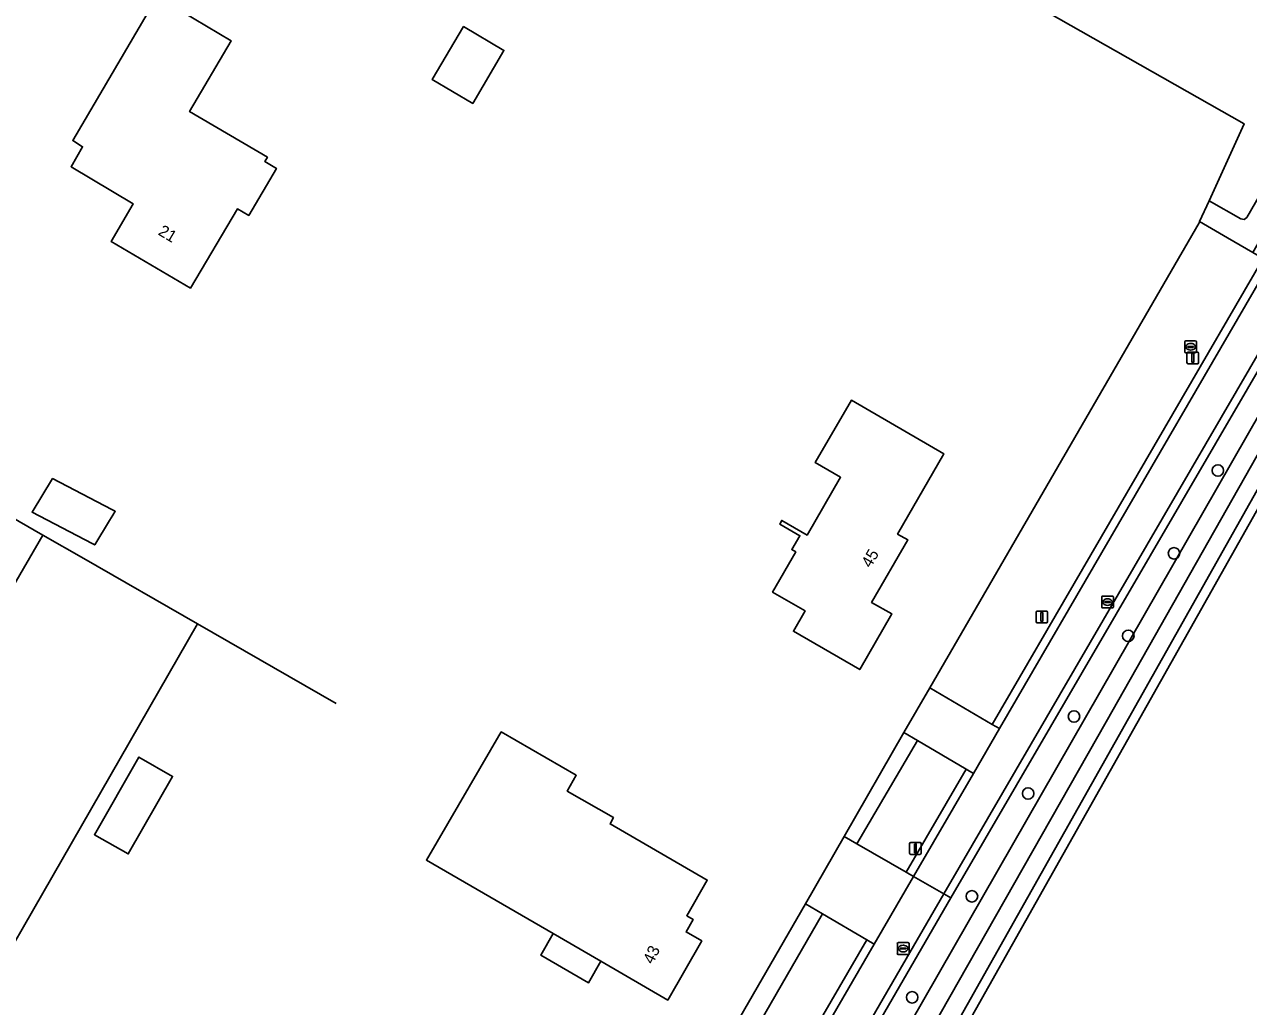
# Model space of a CAD drawing. Extents: x 156502 to 159075, y 384229 to 386100.
# Drawn here: x 157270.5 to 157374.9, y 385779.8 to 385863.6 of the extents above; entities that cross this region are included whole.
import ezdxf

# ---------------------------------------------------------------- set-up
doc = ezdxf.new("R2010")
doc.units = 0
for name, color, linetype in [('IMGEO_Boom', 7, 'Continuous'), ('IMGEO_Erf', 7, 'Continuous'), ('IMGEO_Gemengd_bos', 7, 'Continuous'), ('IMGEO_Grasland_overig', 7, 'Continuous'), ('IMGEO_Greppel_droge_sloot', 7, 'Continuous'), ('IMGEO_Groenvoorziening', 7, 'Continuous'), ('IMGEO_Hek', 7, 'Continuous'), ('IMGEO_Lichtmast', 7, 'Continuous'), ('IMGEO_Oever', 7, 'Continuous'), ('IMGEO_Pand', 7, 'Continuous'), ('IMGEO_Pand_nummerreeks', 7, 'Continuous'), ('IMGEO_Pand_overbouw', 7, 'Continuous'), ('IMGEO_Rijbaan_lokaal_gesloten', 7, 'Continuous'), ('IMGEO_Rijbaan_lokaal_halfverhard', 7, 'Continuous'), ('IMGEO_Rijbaan_lokaal_open', 7, 'Continuous'), ('IMGEO_Rioolput', 7, 'Continuous')]:
    doc.layers.add(name, color=color, linetype=linetype)

msp = doc.modelspace()

# ---------------------------------------------------------------- linework, layer by layer
at = {"layer": 'IMGEO_Boom'}
for centre in [(157372.3, 385825.54), (157368.55, 385818.48), (157364.65, 385811.44), (157360.02, 385804.56), (157356.1, 385798), (157351.31, 385789.23), (157346.21, 385780.62)]:
    msp.add_circle(centre, 0.489, dxfattribs=at)
at = {"layer": 'IMGEO_Erf'}
msp.add_lwpolyline([(157260.44, 385826.72), (157272.04, 385820.04), (157275.52, 385818.05), (157285.22, 385812.46), (157254.63, 385759.26), (157295.91, 385735.36), (157303.57, 385730.97), (157303.66, 385730.92), (157313.86, 385748.5), (157317.18, 385754.23), (157317.26, 385754.36), (157320.72, 385760.25), (157337.11, 385788.6), (157340.4, 385794.34), (157345.49, 385803.19), (157347.71, 385807.02), (157370.69, 385846.65), (157370.74, 385846.77), (157371.55, 385848.55), (157374.53, 385855.11), (157336.95, 385876.45)], dxfattribs=at)
for points in [[(157281.78, 385865.95), (157288.1, 385862.19), (157284.56, 385856.15), (157291.2, 385852.25), (157290.98, 385851.88), (157291.96, 385851.3), (157289.6, 385847.29), (157288.63, 385847.85), (157284.62, 385841.1), (157277.86, 385845.08), (157279.74, 385848.29), (157274.44, 385851.45), (157275.43, 385853.15), (157274.59, 385853.67)], [(157307.93, 385863.4), (157311.38, 385861.36), (157308.71, 385856.84), (157305.26, 385858.88)], [(157341.02, 385831.54), (157348.92, 385826.96), (157344.96, 385820.12), (157345.83, 385819.63), (157342.75, 385814.3), (157344.48, 385813.31), (157341.74, 385808.56), (157336.08, 385811.83), (157337.08, 385813.57), (157334.3, 385815.17), (157336.28, 385818.6), (157335.94, 385818.8), (157336.63, 385819.98), (157334.91, 385820.98), (157335.08, 385821.29), (157337.24, 385820.04), (157340.1, 385824.97), (157337.94, 385826.22)], [(157277.91, 385822.23), (157278.21, 385822.07), (157278, 385821.73), (157277.73, 385821.28), (157276.46, 385819.2), (157276.24, 385819.31), (157271.12, 385821.98), (157272.87, 385824.85)], [(157317.55, 385799.56), (157316.78, 385798.21), (157320.72, 385795.94), (157320.43, 385795.41), (157328.72, 385790.61), (157326.97, 385787.58), (157327.53, 385787.24), (157326.92, 385786.2), (157328.26, 385785.43), (157325.36, 385780.38), (157319.65, 385783.69), (157315.58, 385786.05), (157304.76, 385792.32), (157311.15, 385803.25)], [(157280.23, 385801.1), (157283.1, 385799.46), (157279.32, 385792.84), (157276.44, 385794.48)]]:
    msp.add_lwpolyline(points, close=True, dxfattribs=at)
at = {"layer": 'IMGEO_Gemengd_bos'}
for points in [[(157202.77, 386052.01), (157197.24, 386050.03), (157178.39, 386025.76), (157218.89, 386000), (157265.45, 385970.38), (157240.01, 385933.44), (157257.61, 385922.62), (157291.8, 385905.79), (157297.29, 385911.48), (157341.88, 385885.73), (157336.95, 385876.45), (157374.53, 385855.11), (157371.55, 385848.55), (157374.24, 385846.99), (157374.53, 385846.95), (157374.77, 385847.13), (157419.09, 385923.89)], [(157458.7, 385822.57), (157423.67, 385843.01), (157401.01, 385856.04), (157400.45, 385856.36), (157400.33, 385856.13), (157400.02, 385856.3), (157396.13, 385858.5), (157395.47, 385857.33), (157372.59, 385816.74), (157334.96, 385750), (157287.88, 385668.68), (157271.39, 385640.19), (157191.03, 385500)]]:
    msp.add_lwpolyline(points, dxfattribs=at)
msp.add_lwpolyline([(157285.22, 385812.46), (157275.52, 385818.05), (157272.04, 385820.04), (157246.93, 385776.79), (157242.96, 385769.96), (157222.97, 385734.27), (157232.44, 385728.12), (157250.89, 385753.43), (157300.61, 385725.63), (157300.68, 385725.75), (157301.99, 385728.11), (157303.57, 385730.97), (157295.91, 385735.36), (157254.63, 385759.26)], close=True, dxfattribs=at)
at = {"layer": 'IMGEO_Grasland_overig'}
for points in [[(157272.04, 385820.04), (157260.44, 385826.72), (157250.7, 385832.31), (157250.46, 385831.88), (157205.7, 385857.93)], [(157186.51, 385823.49), (157214.2, 385807.37), (157215.15, 385806.82), (157210.12, 385798.13), (157215.69, 385794.81), (157216.71, 385794.2), (157246.93, 385776.79), (157272.04, 385820.04)]]:
    msp.add_lwpolyline(points, dxfattribs=at)
at = {"layer": 'IMGEO_Greppel_droge_sloot'}
for points in [[(157419.09, 385923.89), (157374.77, 385847.13), (157374.53, 385846.95), (157374.24, 385846.99), (157371.55, 385848.55), (157370.74, 385846.77), (157373.11, 385845.39), (157375.29, 385844.13), (157410.37, 385905.3), (157420.59, 385922.78), (157421.74, 385925.12)], [(157393.36, 385858.05), (157393.11, 385857.61), (157362.75, 385804.11), (157325.82, 385739.17), (157293.92, 385684.22), (157277.51, 385655.56), (157259.26, 385623.71), (157238.62, 385587.75), (157224.85, 385563.79), (157203.07, 385525.9), (157174.27, 385475.36), (157161.25, 385452.05), (157151.08, 385433.93), (157146.7, 385427.27), (157144.86, 385424.97)], [(157146.46, 385424.36), (157148.98, 385428.05), (157150.58, 385430.99), (157151.89, 385433.4), (157190.31, 385500.41), (157270.67, 385640.6), (157287.16, 385669.09), (157334.24, 385750.41), (157371.86, 385817.15), (157394.6, 385857.47)]]:
    msp.add_lwpolyline(points, dxfattribs=at)
at = {"layer": 'IMGEO_Groenvoorziening'}
for points in [[(157395.47, 385857.33), (157396.13, 385858.5), (157400.02, 385856.3), (157400.33, 385856.13), (157400.45, 385856.36), (157394.87, 385860.03), (157394.47, 385860.19), (157394.07, 385860.35), (157391.83, 385861.67), (157349.52, 385789.09), (157310.6, 385721.93), (157305.61, 385713.27), (157297.81, 385699.74), (157287.9, 385682.57), (157281.97, 385672.23), (157284.2, 385670.89), (157329.73, 385750)], [(157329.73, 385750), (157392.25, 385858.97)]]:
    msp.add_lwpolyline(points, dxfattribs=at)
for points in [[(157347.71, 385807.02), (157353.05, 385803.89), (157376.15, 385843.62), (157375.29, 385844.13), (157373.11, 385845.39), (157370.74, 385846.77), (157370.69, 385846.65)], [(157346.66, 385802.51), (157345.49, 385803.19), (157340.4, 385794.34), (157341.5, 385793.71)], [(157350.82, 385800.07), (157346.66, 385802.51), (157341.5, 385793.71), (157345.7, 385791.29)], [(157338.56, 385787.75), (157337.11, 385788.6), (157320.72, 385760.25), (157317.26, 385754.36), (157318.78, 385753.48)], [(157342.35, 385785.53), (157338.56, 385787.75), (157318.78, 385753.48), (157322.45, 385751.34)]]:
    msp.add_lwpolyline(points, close=True, dxfattribs=at)
at = {"layer": 'IMGEO_Hek'}
for points in [[(157240.01, 385933.44), (157257.61, 385922.62), (157291.8, 385905.79), (157297.29, 385911.48), (157341.88, 385885.73), (157336.95, 385876.45), (157374.53, 385855.11), (157371.55, 385848.55)], [(157372.59, 385816.74), (157395.47, 385857.33)], [(157371.55, 385848.55), (157370.74, 385846.77)], [(157370.74, 385846.77), (157370.69, 385846.65), (157347.71, 385807.02)], [(157260.44, 385826.72), (157272.04, 385820.04)], [(157272.04, 385820.04), (157275.52, 385818.05)], [(157275.52, 385818.05), (157285.22, 385812.46)], [(157334.96, 385750), (157372.59, 385816.74)], [(157295.91, 385735.36), (157254.63, 385759.26), (157285.22, 385812.46)], [(157285.22, 385812.46), (157297.05, 385805.66)], [(157347.71, 385807.02), (157345.49, 385803.19)], [(157345.49, 385803.19), (157340.4, 385794.34)], [(157320.72, 385760.25), (157337.11, 385788.6)]]:
    msp.add_lwpolyline(points, dxfattribs=at)
at = {"layer": 'IMGEO_Lichtmast'}
for p, q in [((157369.76, 385835.64), (157370.55, 385835.64)), ((157370.55, 385835.64), (157369.76, 385835.64)), ((157369.66, 385834.74), (157369.66, 385835.54)), ((157369.66, 385835.54), (157369.66, 385834.74)), ((157370.55, 385834.64), (157369.76, 385834.64)), ((157369.76, 385834.64), (157370.55, 385834.64)), ((157370.65, 385835.54), (157370.65, 385834.74)), ((157370.65, 385834.74), (157370.65, 385835.54)), ((157356.78, 385812.66), (157356.78, 385813.46)), ((157356.78, 385813.46), (157356.78, 385812.66)), ((157356.88, 385813.56), (157357.67, 385813.56)), ((157357.67, 385813.56), (157356.88, 385813.56)), ((157357.77, 385813.46), (157357.77, 385812.66)), ((157357.77, 385812.66), (157357.77, 385813.46)), ((157357.67, 385812.56), (157356.88, 385812.56)), ((157356.88, 385812.56), (157357.67, 385812.56)), ((157345.99, 385792.91), (157345.99, 385793.71)), ((157345.99, 385793.71), (157345.99, 385792.91)), ((157346.09, 385793.81), (157346.88, 385793.81)), ((157346.88, 385793.81), (157346.09, 385793.81)), ((157346.88, 385792.81), (157346.09, 385792.81)), ((157346.09, 385792.81), (157346.88, 385792.81)), ((157346.98, 385793.71), (157346.98, 385792.91)), ((157346.98, 385792.91), (157346.98, 385793.71))]:
    msp.add_line(p, q, dxfattribs=at)
for points in [[(157370.08, 385835.52), (157370.23, 385835.52), (157370.23, 385834.77), (157370.08, 385834.77), (157370.08, 385835.52)], [(157357.2, 385813.43), (157357.35, 385813.43), (157357.35, 385812.68), (157357.2, 385812.68), (157357.2, 385813.43)], [(157346.41, 385793.69), (157346.56, 385793.69), (157346.56, 385792.94), (157346.41, 385792.94), (157346.41, 385793.69)]]:
    msp.add_lwpolyline(points, dxfattribs=at)
for centre, start, end in [((157369.76, 385835.54), 90, 180), ((157369.76, 385835.54), 90, 180), ((157370.55, 385835.54), 0, 90), ((157370.55, 385835.54), 360, 90), ((157369.76, 385834.74), 180, 270), ((157369.76, 385834.74), 180, 270), ((157370.55, 385834.74), 270, 0), ((157370.55, 385834.74), 270, 0), ((157356.88, 385813.46), 90, 180), ((157356.88, 385813.46), 90, 180), ((157356.88, 385812.66), 180, 270), ((157356.88, 385812.66), 180, 270), ((157357.67, 385813.46), 0, 90), ((157357.67, 385813.46), 360, 90), ((157357.67, 385812.66), 270, 0), ((157357.67, 385812.66), 270, 0), ((157346.09, 385793.71), 90, 180), ((157346.09, 385793.71), 90, 180), ((157346.09, 385792.91), 180, 270), ((157346.09, 385792.91), 180, 270), ((157346.88, 385793.71), 0, 90), ((157346.88, 385793.71), 360, 90), ((157346.88, 385792.91), 270, 0), ((157346.88, 385792.91), 270, 0)]:
    msp.add_arc(centre, 0.1, start, end, dxfattribs=at)
at = {"layer": 'IMGEO_Oever'}
for points in [[(157392.25, 385858.97), (157329.73, 385750), (157284.2, 385670.89), (157172.1, 385476.13), (157169.19, 385471.06), (157144.41, 385428.01), (157142.39, 385426.07), (157140.63, 385424.94), (157139.2, 385424.57), (157138.03, 385424.77), (157136.95, 385425.17), (157066.81, 385467.26), (157031.92, 385488.2), (156971.45, 385524.49), (156960.96, 385531.06), (156958.28, 385532.65)], [(157144.86, 385424.97), (157146.7, 385427.27), (157151.08, 385433.93), (157161.25, 385452.05), (157174.27, 385475.36), (157203.07, 385525.9), (157224.85, 385563.79), (157238.62, 385587.75), (157259.26, 385623.71), (157277.51, 385655.56), (157293.92, 385684.22), (157325.82, 385739.17), (157362.75, 385804.11), (157393.11, 385857.61), (157393.36, 385858.05)], [(157146.17, 385421.74), (157150.67, 385429.59), (157152.55, 385432.88), (157191.03, 385500), (157271.39, 385640.19), (157287.88, 385668.68), (157334.96, 385750), (157372.59, 385816.74), (157395.47, 385857.33)], [(157394.6, 385857.47), (157371.86, 385817.15), (157334.24, 385750.41), (157287.16, 385669.09), (157270.67, 385640.6), (157190.31, 385500.41), (157151.89, 385433.4), (157150.58, 385430.99), (157148.98, 385428.05), (157146.46, 385424.36)]]:
    msp.add_lwpolyline(points, dxfattribs=at)
at = {"layer": 'IMGEO_Pand'}
for points in [[(157281.78, 385865.95), (157274.59, 385853.67), (157275.43, 385853.15), (157274.44, 385851.45), (157279.74, 385848.29), (157277.86, 385845.08), (157284.62, 385841.1), (157288.63, 385847.85), (157289.6, 385847.29), (157291.96, 385851.3), (157290.98, 385851.88), (157291.2, 385852.25), (157284.56, 385856.15), (157288.1, 385862.19)], [(157305.26, 385858.88), (157308.71, 385856.84), (157311.38, 385861.36), (157307.93, 385863.4)], [(157348.92, 385826.96), (157341.02, 385831.54), (157337.94, 385826.22), (157340.1, 385824.97), (157337.24, 385820.04), (157335.08, 385821.29), (157334.91, 385820.98), (157336.63, 385819.98), (157335.94, 385818.8), (157336.28, 385818.6), (157334.3, 385815.17), (157337.08, 385813.57), (157336.08, 385811.83), (157341.74, 385808.56), (157344.48, 385813.31), (157342.75, 385814.3), (157345.83, 385819.63), (157344.96, 385820.12)], [(157272.87, 385824.85), (157271.12, 385821.98), (157276.24, 385819.31), (157276.46, 385819.2), (157277.73, 385821.28), (157278, 385821.73), (157278.21, 385822.07), (157277.91, 385822.23)], [(157320.43, 385795.41), (157320.72, 385795.94), (157316.78, 385798.21), (157317.55, 385799.56), (157311.15, 385803.25), (157304.76, 385792.32), (157315.58, 385786.05), (157319.65, 385783.69), (157325.36, 385780.38), (157328.26, 385785.43), (157326.92, 385786.2), (157327.53, 385787.24), (157326.97, 385787.58), (157328.72, 385790.61)], [(157283.1, 385799.46), (157280.23, 385801.1), (157276.44, 385794.48), (157279.32, 385792.84)]]:
    msp.add_lwpolyline(points, close=True, dxfattribs=at)
at = {"layer": 'IMGEO_Pand_overbouw'}
msp.add_lwpolyline([(157315.58, 385786.05), (157314.52, 385784.22), (157318.6, 385781.86), (157319.65, 385783.69)], close=True, dxfattribs=at)
at = {"layer": 'IMGEO_Rijbaan_lokaal_gesloten'}
msp.add_lwpolyline([(157348.91, 385789.44), (157391.21, 385862.03), (157396.12, 385870.48), (157427.36, 385924.19), (157427.79, 385923.96), (157432.64, 385928.52), (157423.54, 385933.72), (157425.1, 385927.64), (157424.2, 385926.06), (157424.73, 385925.73), (157353.67, 385803.53), (157351.44, 385799.71), (157346.33, 385790.92)], close=True, dxfattribs=at)
at = {"layer": 'IMGEO_Rijbaan_lokaal_halfverhard'}
for points in [[(157424.73, 385925.73), (157424.2, 385926.06), (157424.08, 385926.09), (157423.29, 385924.72), (157376.15, 385843.62), (157353.05, 385803.89), (157353.67, 385803.53)], [(157391.83, 385861.67), (157391.21, 385862.03), (157348.91, 385789.44), (157349.52, 385789.09)], [(157353.67, 385803.53), (157353.05, 385803.89), (157347.71, 385807.02), (157345.49, 385803.19), (157346.66, 385802.51), (157350.82, 385800.07), (157351.44, 385799.71)], [(157351.44, 385799.71), (157350.82, 385800.07), (157345.7, 385791.29), (157346.33, 385790.92)], [(157349.52, 385789.09), (157348.91, 385789.44), (157309.98, 385722.29), (157304.98, 385713.63), (157297.19, 385700.1), (157287.28, 385682.93), (157276.98, 385664.99), (157272.99, 385658.15), (157259.7, 385634.92), (157260.02, 385634.73), (157260.32, 385634.56), (157273.62, 385657.79), (157277.6, 385664.64), (157281.97, 385672.23), (157287.9, 385682.57), (157297.81, 385699.74), (157305.61, 385713.27), (157310.6, 385721.93)], [(157342.98, 385785.16), (157342.35, 385785.53), (157322.45, 385751.34), (157323.12, 385750.95)]]:
    msp.add_lwpolyline(points, close=True, dxfattribs=at)
at = {"layer": 'IMGEO_Rijbaan_lokaal_open'}
msp.add_lwpolyline([(157346.33, 385790.92), (157345.7, 385791.29), (157341.5, 385793.71), (157340.4, 385794.34), (157337.11, 385788.6), (157338.56, 385787.75), (157342.35, 385785.53), (157342.98, 385785.16)], close=True, dxfattribs=at)
for points in [[(157348.91, 385789.44), (157346.33, 385790.92), (157342.98, 385785.16), (157323.12, 385750.95), (157319.61, 385745.16), (157307.23, 385723.61), (157303.78, 385717.63), (157302.35, 385715.15), (157300.61, 385712.13), (157299.17, 385709.62), (157298.29, 385708.09), (157294.28, 385701.12), (157284.95, 385684.91), (157274.19, 385666.22), (157272.92, 385664.02), (157270.01, 385658.98), (157269.67, 385658.4), (157266.46, 385652.88), (157264.81, 385649.96)], [(157258.5, 385639.01), (157257.01, 385636.46), (157259.7, 385634.92), (157272.99, 385658.15), (157276.98, 385664.99), (157287.28, 385682.93), (157297.19, 385700.1), (157304.98, 385713.63), (157309.98, 385722.29), (157348.91, 385789.44)]]:
    msp.add_lwpolyline(points, dxfattribs=at)
at = {"layer": 'IMGEO_Rioolput'}
for p, q in [((157369.48, 385835.66), (157369.48, 385836.51)), ((157369.55, 385836.59), (157370.4, 385836.59)), ((157369.73, 385836.08), (157369.73, 385836.09)), ((157370.17, 385836.04), (157369.77, 385836.04)), ((157369.78, 385836.13), (157370.18, 385836.13)), ((157369.96, 385836.37), (157369.99, 385836.37)), ((157369.99, 385835.81), (157369.96, 385835.81)), ((157370.22, 385836.09), (157370.22, 385836.08)), ((157370.48, 385836.51), (157370.48, 385835.66)), ((157370.4, 385835.59), (157369.55, 385835.59)), ((157362.38, 385813.9), (157362.38, 385814.75)), ((157362.45, 385814.83), (157363.31, 385814.83)), ((157363.38, 385814.75), (157363.38, 385813.9)), ((157363.31, 385813.82), (157362.45, 385813.82)), ((157362.64, 385814.32), (157362.64, 385814.33)), ((157362.68, 385814.37), (157363.08, 385814.37)), ((157363.08, 385814.28), (157362.68, 385814.28)), ((157362.87, 385814.6), (157362.89, 385814.6)), ((157362.89, 385814.05), (157362.87, 385814.05)), ((157363.12, 385814.33), (157363.12, 385814.32)), ((157344.95, 385784.35), (157344.95, 385785.21)), ((157345.02, 385785.28), (157345.87, 385785.28)), ((157345.2, 385784.77), (157345.2, 385784.79)), ((157345.64, 385784.74), (157345.24, 385784.74)), ((157345.25, 385784.82), (157345.64, 385784.82)), ((157345.43, 385785.06), (157345.46, 385785.06)), ((157345.46, 385784.5), (157345.43, 385784.5)), ((157345.69, 385784.79), (157345.69, 385784.77)), ((157345.95, 385785.21), (157345.95, 385784.35)), ((157345.87, 385784.28), (157345.02, 385784.28))]:
    msp.add_line(p, q, dxfattribs=at)
for points in [[(157369.48, 385835.66), (157369.48, 385836.51)], [(157369.55, 385836.59), (157370.4, 385836.59)], [(157370.48, 385836.51), (157370.48, 385835.66)], [(157370.4, 385835.59), (157369.55, 385835.59)], [(157362.38, 385813.9), (157362.38, 385814.75)], [(157362.45, 385814.83), (157363.31, 385814.83)], [(157363.38, 385814.75), (157363.38, 385813.9)], [(157363.31, 385813.82), (157362.45, 385813.82)], [(157344.95, 385784.35), (157344.95, 385785.21)], [(157345.02, 385785.28), (157345.87, 385785.28)], [(157345.95, 385785.21), (157345.95, 385784.35)], [(157345.87, 385784.28), (157345.02, 385784.28)]]:
    msp.add_lwpolyline(points, dxfattribs=at)
for centre, radius, start, end in [((157369.55, 385836.51), 0.0765, 91.552, 178.448), ((157369.55, 385836.51), 0.0765, 91.552, 178.448), ((157369.55, 385835.66), 0.0765, 181.552, 268.448), ((157369.55, 385835.66), 0.0765, 181.552, 268.448), ((157369.78, 385836.09), 0.0403, 85.8775, 175.7526), ((157369.77, 385836.08), 0.0366, 178.938, 274.7102), ((157370.18, 385836.09), 0.043, 264.8664, 352.4533), ((157370.18, 385836.09), 0.0386, 1.7309, 96.639), ((157370.4, 385836.51), 0.0765, 1.552, 88.448), ((157370.4, 385836.51), 0.0765, 1.552, 88.448), ((157370.4, 385835.66), 0.0765, 271.552, 358.448), ((157370.4, 385835.66), 0.0765, 271.552, 358.448), ((157362.46, 385814.75), 0.0765, 91.552, 178.448), ((157362.46, 385814.75), 0.0765, 91.552, 178.448), ((157363.3, 385814.75), 0.0765, 1.552, 88.448), ((157363.3, 385814.75), 0.0765, 1.552, 88.448), ((157362.46, 385813.9), 0.0765, 181.552, 268.448), ((157362.46, 385813.9), 0.0765, 181.552, 268.448), ((157362.68, 385814.33), 0.0403, 85.8775, 175.7526), ((157362.68, 385814.32), 0.0366, 178.938, 274.7102), ((157363.08, 385814.33), 0.0386, 1.7309, 96.639), ((157363.08, 385814.32), 0.043, 264.8664, 352.4533), ((157363.3, 385813.9), 0.0765, 271.552, 358.448), ((157363.3, 385813.9), 0.0765, 271.552, 358.448), ((157345.02, 385785.2), 0.0765, 91.552, 178.448), ((157345.02, 385785.2), 0.0765, 91.552, 178.448), ((157345.24, 385784.78), 0.0403, 85.8775, 175.7526), ((157345.24, 385784.77), 0.0366, 178.938, 274.7102), ((157345.65, 385784.78), 0.0386, 1.7309, 96.639), ((157345.65, 385784.78), 0.043, 264.8664, 352.4533), ((157345.87, 385785.2), 0.0765, 1.552, 88.448), ((157345.87, 385785.2), 0.0765, 1.552, 88.448), ((157345.02, 385784.35), 0.0765, 181.552, 268.448), ((157345.02, 385784.35), 0.0765, 181.552, 268.448), ((157345.87, 385784.35), 0.0765, 271.552, 358.448), ((157345.87, 385784.35), 0.0765, 271.552, 358.448)]:
    msp.add_arc(centre, radius, start, end, dxfattribs=at)
for centre, major_axis, ratio, start_param, end_param in [((157369.96, 385836.09), (-0.387, 0.002), 0.722429, 4.712389, 7.853982), ((157369.99, 385836.09), (-0.39, 0.002), 0.717154, 1.570796, 4.712389), ((157362.87, 385814.32), (-0.387, 0.002), 0.722429, 4.712389, 7.853982), ((157362.89, 385814.32), (-0.39, 0.002), 0.717154, 1.570796, 4.712389), ((157345.43, 385784.78), (-0.387, 0.002), 0.722429, 4.712389, 7.853982), ((157345.46, 385784.78), (-0.39, 0.002), 0.717154, 1.570796, 4.712389)]:
    msp.add_ellipse(centre, major_axis=major_axis, ratio=ratio, start_param=start_param, end_param=end_param, dxfattribs=at)

# ---------------------------------------------------------------- texts
at = {"layer": 'IMGEO_Pand_nummerreeks'}
for s, rotation, p in [('21', 329.3275, (157281.8, 385845.69)), ('45', 60.0059, (157342.67, 385817.17)), ('43', 64.0624, (157324.08, 385783.38))]:
    msp.add_text(s, height=1, rotation=rotation, dxfattribs=at).set_placement(p)

doc.saveas('drawing.dxf')
